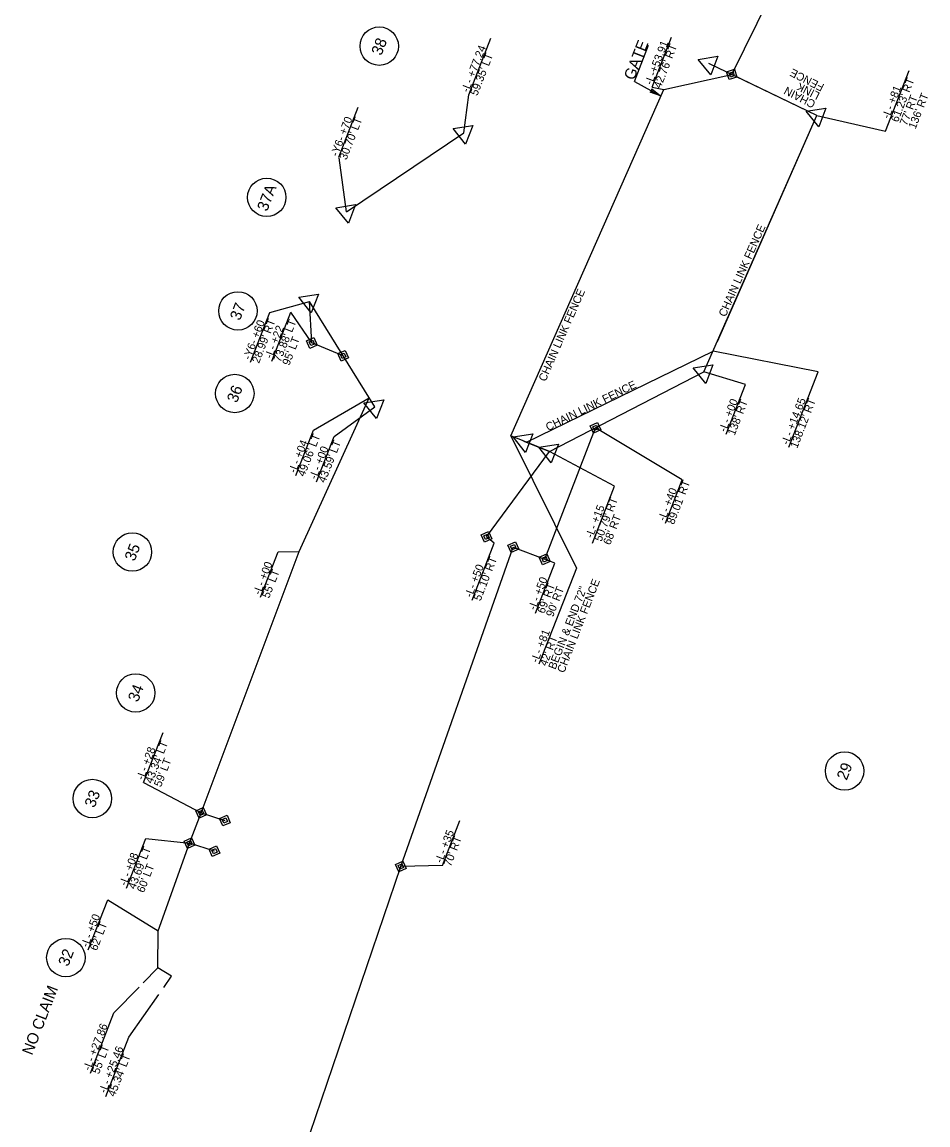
# Model space of a CAD drawing. Extents: x 1975689 to 1978251, y 778490 to 782347.
# Drawn here: x 1977425 to 1977991, y 781309 to 781998 of the extents above; entities that cross this region are included whole.
import ezdxf

# ---------------------------------------------------------------- set-up
doc = ezdxf.new("R2010")
doc.units = 0
for name, color, linetype in [('Prop Dimension', 7, 'Continuous'), ('Prop Dimension Text', 7, 'Continuous'), ('Prop Easement Construction', 7, 'Continuous'), ('Prop Easement Construction Station Offsets', 7, 'Continuous'), ('Prop Easement Permanent Drainage', 7, 'Continuous'), ('Prop Easement Permanent Drainage Station Offsets', 7, 'Continuous'), ('Prop Easement Permanent Drainage Utility', 7, 'Continuous'), ('Prop Easement Permanent Drainage Utility Station Offsets', 7, 'Continuous'), ('Prop Easement Permanent Utility', 7, 'Continuous'), ('Prop Easement Permanent Utility Station Offsets', 7, 'Continuous'), ('Prop Fence Chain Link', 7, 'Continuous'), ('Prop Parcel Number CELL', 7, 'Continuous'), ('Prop ROW Marker CELL', 7, 'Continuous'), ('Prop ROW Permanent Easement CELL', 7, 'Continuous'), ('Prop ROW RW CA Lines', 7, 'Continuous'), ('Prop ROW RW Lines', 7, 'Continuous'), ('Prop ROW Station Offsets', 7, 'Continuous'), ('Prop Terminator CELL', 7, 'Continuous')]:
    doc.layers.add(name, color=color, linetype=linetype)

msp = doc.modelspace()

# ---------------------------------------------------------------- linework, layer by layer
at = {"layer": 'Prop Dimension'}
for q in [(1977816.35, 781983.38), (1977823.86, 781951.83)]:
    msp.add_line((1977807.57, 781960.72), q, dxfattribs=at)
at = {"layer": 'Prop Easement Construction'}
for p, q in [((1977598.28, 781667.17), (1977641.82, 781763.21)), ((1977536.97, 781503.93), (1977598.28, 781667.17)), ((1977510.13, 781430.28), (1977529.77, 781484.95)), ((1977510.04, 781407.06), (1977510.13, 781430.28)), ((1977518.5, 781401.82), (1977510.04, 781407.06))]:
    msp.add_line(p, q, dxfattribs=at)
at = {"layer": 'Prop Easement Construction Station Offsets'}
for p, q in [((1977607.22, 781742.97), (1977641.82, 781763.21)), ((1977596.16, 781714.53), (1977607.22, 781742.97)), ((1977574.09, 781638.53), (1977585.15, 781666.96)), ((1977585.15, 781666.96), (1977598.28, 781667.17)), ((1977466.5, 781418.41), (1977478.64, 781449.62)), ((1977478.64, 781449.62), (1977510.13, 781430.28)), ((1977500.83, 781397.7), (1977510.04, 781407.06)), ((1977513.67, 781394.91), (1977518.5, 781401.82)), ((1977482.48, 781379.05), (1977498.22, 781395.05)), ((1977491.96, 781363.79), (1977510.58, 781390.48)), ((1977467.82, 781341.36), (1977482.48, 781379.05)), ((1977477.56, 781326.76), (1977491.96, 781363.79))]:
    msp.add_line(p, q, dxfattribs=at)
at = {"layer": 'Prop Easement Permanent Drainage'}
for p, q in [((1977606.08, 781797.39), (1977604.7, 781823.38)), ((1977625.64, 781789.44), (1977606.08, 781797.39)), ((1977529.77, 781484.95), (1977536.97, 781503.93)), ((1977536.97, 781503.93), (1977551.85, 781499.07)), ((1977545.29, 781479.95), (1977529.77, 781484.95))]:
    msp.add_line(p, q, dxfattribs=at)
at = {"layer": 'Prop Easement Permanent Drainage Station Offsets'}
for p, q in [((1977581.2, 781786.05), (1977593.07, 781816.57)), ((1977606.08, 781797.39), (1977593.07, 781816.57)), ((1977501.07, 781522.8), (1977513.21, 781554.01)), ((1977501.07, 781522.8), (1977536.97, 781503.93)), ((1977490.38, 781456.76), (1977502.52, 781487.97)), ((1977502.52, 781487.97), (1977529.77, 781484.95))]:
    msp.add_line(p, q, dxfattribs=at)
at = {"layer": 'Prop Easement Permanent Drainage Utility'}
msp.add_line((1977715.23, 781676.28), (1977754.5, 781729.66), dxfattribs=at)
at = {"layer": 'Prop Easement Permanent Drainage Utility Station Offsets'}
for p, q in [((1977706.15, 781636.79), (1977719.91, 781672.32)), ((1977719.91, 781672.32), (1977715.23, 781676.28))]:
    msp.add_line(p, q, dxfattribs=at)
at = {"layer": 'Prop Easement Permanent Utility'}
for p, q in [((1977868.32, 781965.11), (1977964.84, 782159.84)), ((1977751.51, 781662.26), (1977783.22, 781744.44)), ((1977661.73, 781470.4), (1977731.92, 781669.83)), ((1977731.92, 781669.83), (1977751.51, 781662.26)), ((1977561.58, 781176.39), (1977661.73, 781470.4))]:
    msp.add_line(p, q, dxfattribs=at)
at = {"layer": 'Prop Easement Permanent Utility Station Offsets'}
for p, q in [((1977837.43, 781711.9), (1977783.22, 781744.44)), ((1977826.9, 781684.74), (1977837.43, 781711.9)), ((1977745.7, 781628.73), (1977757.78, 781659.91)), ((1977757.78, 781659.91), (1977751.51, 781662.26)), ((1977687.63, 781471.1), (1977698.48, 781499.11)), ((1977687.63, 781471.1), (1977661.73, 781470.4))]:
    msp.add_line(p, q, dxfattribs=at)
at = {"layer": 'Prop Fence Chain Link'}
for p, q in [((1977825.93, 781955.72), (1977868.32, 781965.11)), ((1977921.51, 781939.57), (1977868.32, 781965.11)), ((1977730.4, 781739.4), (1977825.93, 781955.72)), ((1977859.33, 781798.27), (1977921.51, 781939.57)), ((1977740.22, 781735.43), (1977856.69, 781792.28)), ((1977754.5, 781729.66), (1977730.4, 781739.4))]:
    msp.add_line(p, q, dxfattribs=at)
at = {"layer": 'Prop Parcel Number CELL'}
for p, q in [((1977648.21, 781982.79), (1977648.21, 781982.79)), ((1977577.99, 781888.32), (1977577.99, 781888.32)), ((1977559.96, 781817.42), (1977559.96, 781817.42)), ((1977558.03, 781765.83), (1977558.03, 781765.83)), ((1977494.09, 781666.82), (1977494.09, 781666.82)), ((1977496.17, 781578.81), (1977496.17, 781578.81)), ((1977938.78, 781530.06), (1977938.78, 781530.06)), ((1977469.07, 781512.84), (1977469.07, 781512.84)), ((1977452.54, 781413.48), (1977452.54, 781413.48))]:
    msp.add_line(p, q, dxfattribs=at)
for centre in [(1977648.21, 781982.79), (1977577.99, 781888.32), (1977559.96, 781817.42), (1977558.03, 781765.83), (1977494.09, 781666.82), (1977496.17, 781578.81), (1977938.78, 781530.06), (1977469.07, 781512.84), (1977452.54, 781413.48)]:
    msp.add_circle(centre, 12, dxfattribs=at)
at = {"layer": 'Prop ROW Marker CELL'}
for p, q in [((1977854.11, 781971.93), (1977854.11, 781971.93)), ((1977868.32, 781965.11), (1977868.32, 781965.11)), ((1977921.51, 781939.57), (1977921.51, 781939.57)), ((1977701.04, 781928.7), (1977701.04, 781928.7)), ((1977627.87, 781879.29), (1977627.87, 781879.29)), ((1977604.7, 781823.38), (1977604.7, 781823.38)), ((1977606.07, 781797.39), (1977606.07, 781797.39)), ((1977625.64, 781789.44), (1977625.64, 781789.44)), ((1977850.98, 781779.31), (1977850.98, 781779.31)), ((1977645.39, 781757.42), (1977645.39, 781757.42)), ((1977783.22, 781744.44), (1977783.22, 781744.44)), ((1977738.56, 781736.09), (1977738.56, 781736.09)), ((1977754.5, 781729.66), (1977754.5, 781729.66)), ((1977715.23, 781676.28), (1977715.23, 781676.28)), ((1977731.92, 781669.83), (1977731.92, 781669.83)), ((1977751.51, 781662.26), (1977751.51, 781662.26)), ((1977536.97, 781503.93), (1977536.97, 781503.93)), ((1977551.85, 781499.07), (1977551.85, 781499.07)), ((1977529.76, 781484.95), (1977529.76, 781484.95)), ((1977545.29, 781479.95), (1977545.29, 781479.95)), ((1977661.73, 781470.4), (1977661.73, 781470.4))]:
    msp.add_line(p, q, dxfattribs=at)
for points in [[(1977855.21, 781964.8), (1977847.4, 781974.53), (1977859.73, 781976.46)], [(1977922.61, 781932.44), (1977914.8, 781942.17), (1977927.13, 781944.1)], [(1977702.14, 781921.57), (1977694.33, 781931.3), (1977706.66, 781933.23)], [(1977628.97, 781872.16), (1977621.15, 781881.89), (1977633.48, 781883.81)], [(1977605.8, 781816.25), (1977597.99, 781825.98), (1977610.32, 781827.91)], [(1977852.08, 781772.18), (1977844.27, 781781.91), (1977856.6, 781783.84)], [(1977646.49, 781750.29), (1977638.68, 781760.02), (1977651.01, 781761.95)], [(1977739.64, 781728.96), (1977731.85, 781738.71), (1977744.18, 781740.61)], [(1977755.6, 781722.53), (1977747.79, 781732.26), (1977760.12, 781734.18)]]:
    msp.add_lwpolyline(points, close=True, dxfattribs=at)
at = {"layer": 'Prop ROW Permanent Easement CELL'}
for points in [[(1977865.11, 781966.74), (1977869.95, 781968.32), (1977871.53, 781963.48), (1977866.69, 781961.9)], [(1977866.72, 781965.92), (1977869.14, 781966.71), (1977869.93, 781964.29), (1977867.51, 781963.5)], [(1977602.72, 781798.69), (1977607.38, 781800.74), (1977609.43, 781796.08), (1977604.77, 781794.03)], [(1977604.4, 781798.04), (1977606.73, 781799.07), (1977607.75, 781796.74), (1977605.42, 781795.71)], [(1977622.29, 781790.74), (1977626.95, 781792.79), (1977629, 781788.13), (1977624.34, 781786.08)], [(1977623.97, 781790.09), (1977626.3, 781791.12), (1977627.32, 781788.79), (1977624.99, 781787.76)], [(1977779.87, 781745.74), (1977784.53, 781747.79), (1977786.58, 781743.13), (1977781.92, 781741.08)], [(1977781.55, 781745.09), (1977783.88, 781746.12), (1977784.9, 781743.79), (1977782.57, 781742.76)], [(1977711.87, 781677.58), (1977716.53, 781679.63), (1977718.58, 781674.97), (1977713.92, 781672.92)], [(1977713.55, 781676.93), (1977715.88, 781677.96), (1977716.9, 781675.63), (1977714.57, 781674.6)], [(1977728.57, 781671.13), (1977733.23, 781673.18), (1977735.28, 781668.52), (1977730.62, 781666.47)], [(1977730.25, 781670.48), (1977732.58, 781671.5), (1977733.6, 781669.17), (1977731.27, 781668.15)], [(1977748.16, 781663.56), (1977752.82, 781665.61), (1977754.87, 781660.95), (1977750.21, 781658.9)], [(1977749.84, 781662.91), (1977752.17, 781663.93), (1977753.19, 781661.61), (1977750.86, 781660.58)], [(1977533.62, 781505.24), (1977538.28, 781507.29), (1977540.33, 781502.63), (1977535.67, 781500.58)], [(1977535.29, 781504.58), (1977537.62, 781505.61), (1977538.65, 781503.28), (1977536.32, 781502.25)], [(1977548.5, 781500.37), (1977553.16, 781502.42), (1977555.21, 781497.76), (1977550.55, 781495.71)], [(1977550.17, 781499.72), (1977552.5, 781500.75), (1977553.53, 781498.42), (1977551.2, 781497.39)], [(1977526.41, 781486.25), (1977531.07, 781488.3), (1977533.12, 781483.64), (1977528.46, 781481.59)], [(1977528.09, 781485.6), (1977530.42, 781486.62), (1977531.44, 781484.29), (1977529.11, 781483.27)], [(1977541.94, 781481.26), (1977546.6, 781483.31), (1977548.65, 781478.65), (1977543.99, 781476.6)], [(1977543.62, 781480.6), (1977545.95, 781481.63), (1977546.97, 781479.3), (1977544.64, 781478.27)], [(1977658.38, 781471.7), (1977663.04, 781473.75), (1977665.09, 781469.09), (1977660.43, 781467.04)], [(1977660.06, 781471.05), (1977662.39, 781472.07), (1977663.41, 781469.74), (1977661.08, 781468.72)]]:
    msp.add_lwpolyline(points, close=True, dxfattribs=at)
at = {"layer": 'Prop ROW RW CA Lines'}
for p, q in [((1977921.51, 781939.57), (1977854.11, 781971.93)), ((1977850.98, 781779.31), (1977921.51, 781939.57)), ((1977754.5, 781729.66), (1977850.98, 781779.31)), ((1977738.55, 781736.11), (1977754.5, 781729.66))]:
    msp.add_line(p, q, dxfattribs=at)
at = {"layer": 'Prop ROW RW Lines'}
for p, q in [((1977627.87, 781879.29), (1977701.04, 781928.7)), ((1977645.39, 781757.42), (1977604.7, 781823.38))]:
    msp.add_line(p, q, dxfattribs=at)
at = {"layer": 'Prop ROW Station Offsets'}
for p, q in [((1977704.06, 781952.41), (1977717.79, 781987.7)), ((1977818.67, 781957.25), (1977830.75, 781988.43)), ((1977964.37, 781929.6), (1977979.1, 781967.61)), ((1977818.67, 781957.25), (1977825.93, 781955.72)), ((1977701.04, 781928.7), (1977704.06, 781952.41)), ((1977622.9, 781913.47), (1977635, 781944.6)), ((1977921.51, 781939.57), (1977964.37, 781929.6)), ((1977627.87, 781879.29), (1977623.22, 781913.02)), ((1977579.88, 781816.43), (1977604.7, 781823.38)), ((1977567.77, 781785.3), (1977579.88, 781816.43)), ((1977922.2, 781779.45), (1977856.69, 781792.28)), ((1977876.98, 781771.53), (1977850.98, 781779.31)), ((1977903.94, 781732.31), (1977922.2, 781779.45)), ((1977864.9, 781740.35), (1977876.98, 781771.53)), ((1977620.13, 781739.07), (1977645.39, 781757.42)), ((1977609.07, 781710.63), (1977620.13, 781739.07)), ((1977730.4, 781739.4), (1977771.47, 781656.79)), ((1977795.12, 781707.94), (1977754.5, 781729.66)), ((1977781.37, 781672.45), (1977795.12, 781707.94)), ((1977771.47, 781656.79), (1977747.88, 781596.82))]:
    msp.add_line(p, q, dxfattribs=at)
at = {"layer": 'Prop Terminator CELL'}
msp.add_lwpolyline([(1977818.49, 781956.09), (1977823.86, 781951.83), (1977817.33, 781954.03), (1977818.66, 781954.67)], close=True, dxfattribs=at)

# ---------------------------------------------------------------- texts
at = {"layer": 'Prop Dimension Text'}
msp.add_text('GATE', height=7, rotation=68.71315, dxfattribs=at).set_placement((1977807.22, 781961.04))
at = {"layer": 'Prop Easement Construction Station Offsets'}
for s, p in [("49.06' LT", (1977601.52, 781713.56)), ('-L- +04', (1977596.03, 781715.7)), ('-L- +00', (1977573.96, 781639.69)), ("55' LT", (1977579.45, 781637.56)), ('-L- +50', (1977466.37, 781419.58)), ("62' LT", (1977471.86, 781417.44)), ('-L- +27.86', (1977467.69, 781342.53)), ("55' LT", (1977473.18, 781340.39)), ('-L- +25.46', (1977477.58, 781328.37)), ("45.34' LT", (1977483.07, 781326.23))]:
    msp.add_text(s, height=5, rotation=68.74567, dxfattribs=at).set_placement(p)
at = {"layer": 'Prop Easement Permanent Drainage Station Offsets'}
for s, p in [("73.88' LT", (1977586.56, 781785.08)), ('-L- +22', (1977581.07, 781787.22)), ("95' LT", (1977592.05, 781782.95)), ("43.34' LT", (1977506.43, 781521.83)), ('-L- +28', (1977500.94, 781523.97)), ("59' LT", (1977511.93, 781519.69)), ("43.69' LT", (1977495.74, 781455.79)), ('-L- +08', (1977490.25, 781457.93)), ("60' LT", (1977501.24, 781453.66))]:
    msp.add_text(s, height=5, rotation=68.74567, dxfattribs=at).set_placement(p)
at = {"layer": 'Prop Easement Permanent Drainage Utility Station Offsets'}
for s, p in [('-L- +50', (1977705.96, 781638.02)), ("51.10' RT", (1977711.46, 781635.89))]:
    msp.add_text(s, height=5, rotation=68.82027, dxfattribs=at).set_placement(p)
at = {"layer": 'Prop Easement Permanent Utility Station Offsets'}
for s, p in [('-L- +40', (1977826.65, 781685.77)), ("89.01' RT", (1977832.15, 781683.65)), ('-L- +50', (1977745.72, 781630.12)), ("69' RT", (1977751.21, 781627.99)), ("90' RT", (1977756.71, 781625.86)), ('-L- +35', (1977687.38, 781472.14)), ("70' RT", (1977692.87, 781470.01))]:
    msp.add_text(s, height=5, rotation=68.82027, dxfattribs=at).set_placement(p)
at = {"layer": 'Prop Fence Chain Link'}
for s, rotation, p in [('FENCE', 152.96266, (1977926.48, 781958.71)), ('CHAIN', 152.96266, (1977921.13, 781948.22)), ('LINK', 152.96266, (1977923.81, 781953.46)), ('CHAIN LINK FENCE', 66.1549, (1977864.45, 781813.28)), ('CHAIN LINK FENCE', 66.37787, (1977752.01, 781772.9)), ('CHAIN LINK FENCE', 26.27546, (1977753.66, 781742.25))]:
    msp.add_text(s, height=5, rotation=rotation, dxfattribs=at).set_placement(p)
at = {"layer": 'Prop Parcel Number CELL'}
for s, p in [('38', (1977649.49, 781976.48)), ('37A', (1977578.17, 781879.18)), ('37', (1977561.19, 781810.96)), ('36', (1977559.31, 781759.53)), ('35', (1977495.42, 781660.64)), ('34', (1977497.52, 781572.67)), ('29', (1977940.08, 781523.8)), ('33', (1977470.41, 781506.66)), ('32', (1977453.96, 781407.51)), ('NO CLAIM', (1977431.43, 781352.12))]:
    msp.add_text(s, height=7, rotation=68.74567, dxfattribs=at).set_placement(p)
at = {"layer": 'Prop ROW Station Offsets'}
for s, rotation, p in [('-L- +77.24', 68.74567, (1977703.93, 781953.57)), ('-L-+53.91', 68.82027, (1977818.48, 781958.18)), ("42.76' RT", 68.82027, (1977823.97, 781956.05)), ("59.35' LT", 68.74567, (1977709.42, 781951.44)), ("61.23' RT", 68.82027, (1977972.07, 781934.91)), ('-L- +81', 68.82027, (1977966.58, 781937.04)), ("77' RT", 68.82027, (1977977.57, 781932.78)), ("136' RT", 68.82027, (1977983.06, 781930.65)), ('-Y6- +70', 68.74567, (1977622.22, 781913.47)), ("30.70' LT", 68.74567, (1977627.71, 781911.33)), ('-Y6- +60', 68.74567, (1977567.64, 781786.47)), ("28.99' RT", 68.74567, (1977573.13, 781784.33)), ('-L- +00', 68.82027, (1977864.65, 781741.39)), ("138' RT", 68.82027, (1977870.14, 781739.26)), ('-L- +14.65', 68.82027, (1977903.69, 781733.35)), ("138.12' RT", 68.82027, (1977909.18, 781731.22)), ("43.59' LT", 68.74567, (1977614.43, 781709.66)), ('-L- +00', 68.74567, (1977608.94, 781711.8)), ("50.79' RT", 68.82027, (1977786.91, 781672.96)), ('-L- +15', 68.82027, (1977781.41, 781675.09)), ("68' RT", 68.82027, (1977792.4, 781670.83)), ('BEGIN & END 72"', 68.82027, (1977758.2, 781593.07)), ('CHAIN LINK FENCE', 68.82027, (1977763.7, 781590.94)), ('-L- +81', 68.82027, (1977747.22, 781597.33)), ("42' RT ", 68.82027, (1977752.71, 781595.2))]:
    msp.add_text(s, height=5, rotation=rotation, dxfattribs=at).set_placement(p)

doc.saveas('drawing.dxf')
